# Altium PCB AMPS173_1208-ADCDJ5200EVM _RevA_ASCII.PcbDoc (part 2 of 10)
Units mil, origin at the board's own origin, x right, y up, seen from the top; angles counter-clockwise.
Board outline 10500 x 2750 mil, 14 copper layers (Top Copper, Layer 2 (GND1), Layer 3 (SIG1), Layer 4 (GND2, Layer 5 (PWR1), Layer 6 (GND3), Layer 7 (PWR/SIGNAL2), Layer 8 (PWR/SIGNAL3), Layer 9 (GND4), Layer 10 PWR2), Layer 11 (GND5), Layer 12 (SIG4), Layer 13 (GND6), Bottom Copper), stack 60.6 mil thick; 701 components, 826 nets, 3386 pads, 2128 vias.
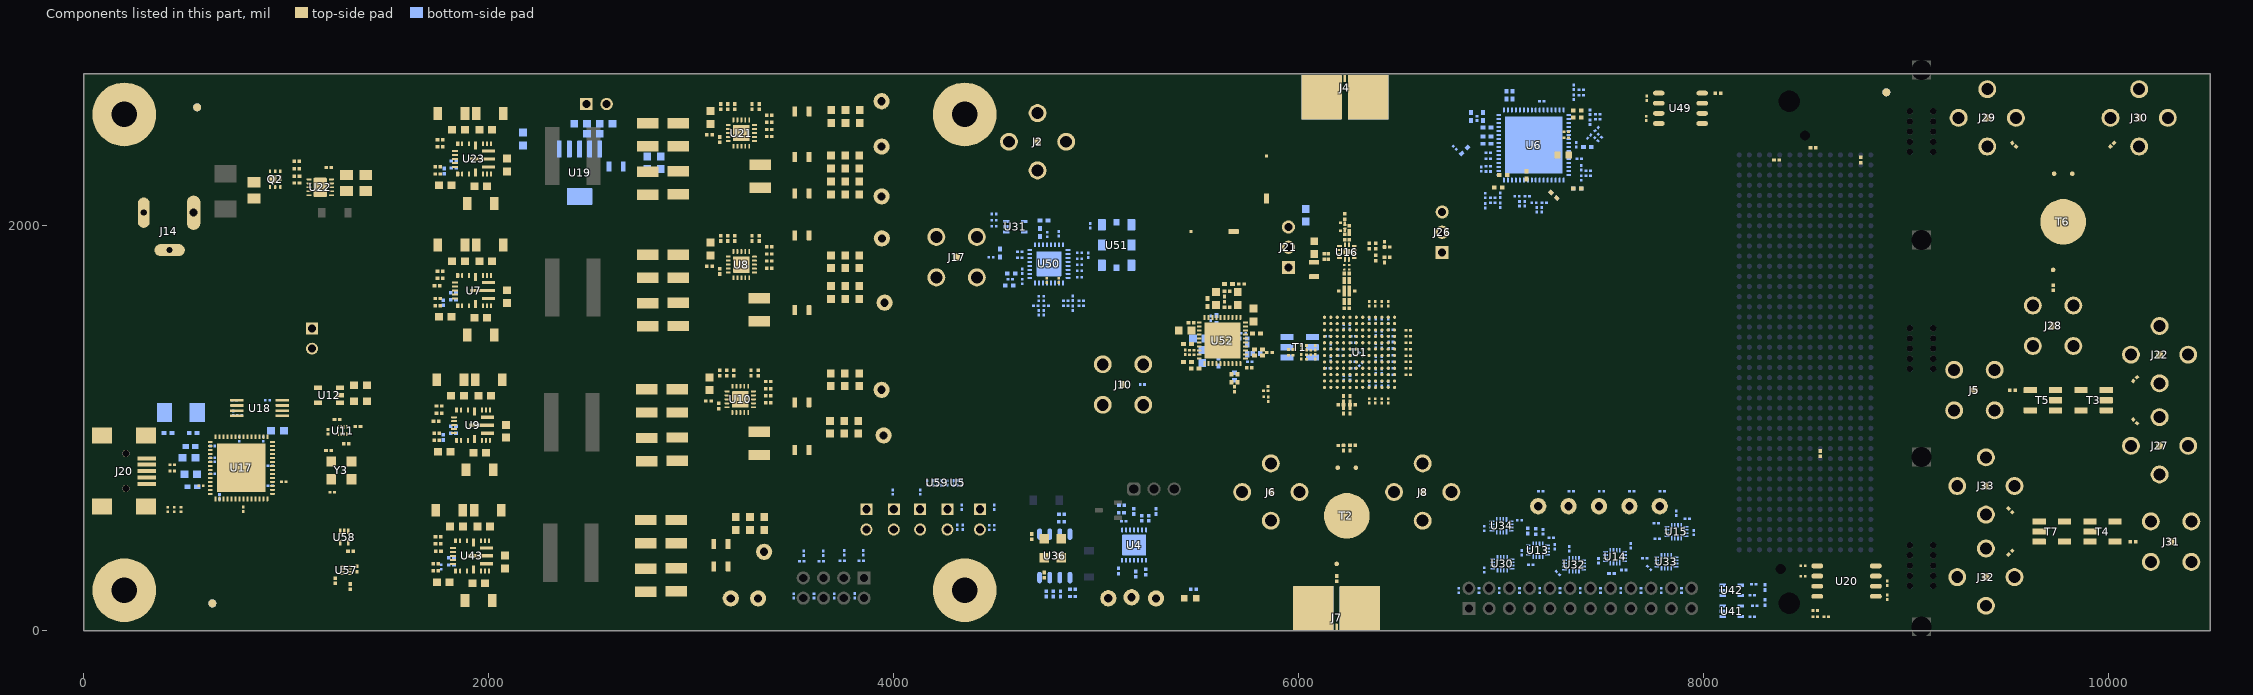
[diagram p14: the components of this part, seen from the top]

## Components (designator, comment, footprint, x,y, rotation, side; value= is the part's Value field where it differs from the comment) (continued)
R37 "CRCW02010000Z0ED" 0201L 7476.02,2550 r0 bottom value=0
R38 "CRCW02010000Z0ED" 0201L 7199.59,2078.93 r270 bottom value=0
R39 "CRCW02010000Z0ED" 0201L 6957.83,2113.09 r180 bottom value=0
R40 "CRCW02010000Z0ED" 0201L 7476.02,2525 r0 bottom value=0
R41 "CRCW02010000Z0ED" 0201L 7174.59,2078.93 r270 bottom value=0
R42 "CRCW02010000Z0ED" 0201L 7430,2271.02 r0 bottom value=0
R43 "RC0201FR-7D10KL" 0201L 7320,2465 r180 top value=10.0k
R44 "CRCW02010000Z0ED" 0201L 7430,2246.02 r0 bottom value=0
R45 "RC0201FR-7D240RL" 0201L 7438.19,2561.12 r270 bottom value=240
R46 "RC0201FR-7D240RL" 0201L 7438.19,2511.12 r90 bottom value=240
R47 "RC0201FR-7D240RL" 0201L 7211.4,2113.93 r180 bottom value=240
R48 "RC0201FR-7D240RL" 0201L 7161.4,2113.93 r0 bottom value=240
R49 "CRCW02010000Z0ED" 0201L 6957.83,2138.09 r180 bottom value=0
R50 "RC0201FR-7D240RL" 0201L 7395,2286.02 r270 bottom value=240
R51 "CRCW02010000Z0ED" 0201L 7487.31,2444.52 r315 bottom value=0
R52 "RC0201FR-7D240RL" 0201L 7395,2236.02 r90 bottom value=240
R53 "CRCW02010000Z0ED" 0201L 7469.63,2426.84 r315 bottom value=0
R54 "CRCW02010000Z0ED" 0201L 7890,198.98 r90 bottom value=0
R55 "RC0201FR-7D240RL" 0201L 7470.85,2477.55 r225 bottom value=240
R56 "RC0201FR-7D240RL" 0201L 7434.03,2440.74 r45 bottom value=240
R57 "RC0201FR-07120RL" 0201L 6995,2101.02 r90 bottom value=120
R58 "RC0201FR-07120RL" 0201L 6995,2151.02 r270 bottom value=120
R59 "CRCW02010000Z0ED" 0201L 7790,198.98 r90 bottom value=0
R60 "RC0201FS-7D100RL" 0201L 4340,511.02 r90 bottom value=100
R61 "RC0201FS-7D100RL" 0201L 7718,2629 r270 top value=100
R62 "CRCW02010000Z0ED" 0201L 7115,2108.98 r270 bottom value=0
R63 "CRCW02010000Z0ED" 0201L 7090,2108.98 r270 bottom value=0
R64 "RC0201FR-7D240RL" 0201L 7127.5,2145 r180 bottom value=240
R65 "RC0201FR-7D240RL" 0201L 7077.5,2145 r0 bottom value=240
R66 "RC0201FS-7D100RL" 0201L 7715,2530 r90 top value=100
R67 "RC0201FS-7D1KL" 0201 4682,465 r270 top value=1.00k
R68 "RC0201FS-7D1KL" 0201 4742.99,274.57 r90 top value=1.00k
R69 "RC0201FR-0747KL" 0201L 4313,511.02 r270 bottom value=47.0k
R70 "CRCW02010000Z0ED" 0201 5755.21,1298.79 r180 top value=27.0
R71 "RC0201FS-7D100RL" 0201L 7645,690 r180 bottom value=100
R72 "CRCW02010000Z0ED" 0201L 7690,198.98 r90 bottom value=0
R73 "CRCW02010000Z0ED" 0201 7130.98,493.39 r270 bottom value=10.0k
R74 "CRCW02010000Z0ED" 0201 7170.98,490.39 r270 bottom value=10.0k
R75 "RC0201FR-7D10KL" 0201L 7205.98,488.39 r270 bottom value=10.0k
R76 "CRCW02010000Z0ED" 0201L 7590,198.98 r90 bottom value=0
R77 "RC0201FR-7D10KL" 0201L 7605,300 r180 bottom value=10.0k
R78 "CRCW02010000Z0ED" 0201 7545,283 r0 bottom value=10.0k
R79 "CRCW02010000Z0ED" 0201L 7490,198.98 r90 bottom value=0
R80 "RC0201FR-7D10KL" 0201L 7765,530 r0 bottom value=10.0k
R81 "RC0201FR-7D10KL" 0201L 7865,580 r270 bottom value=10.0k
R82 "RC0201FS-7D100RL" 0201L 7795,690 r180 bottom value=100
R83 "RC0201FS-7D100RL" 0201L 3848.98,385 r90 bottom value=100
R84 "RC0201FR-0747KL" 0201L 3838.98,345 r0 bottom value=47.0k
R85 "CRCW02010000Z0ED" 0201L 7390,198.98 r90 bottom value=0
R86 "RC0201FR-7D49R9L" 0201L 7335,405 r90 bottom value=27.0
R87 "RC0201FS-7D100RL" 0201L 3755,386.02 r90 bottom value=100
R88 "CRCW02010000Z0ED" 0201L 7290,198.98 r90 bottom value=0
R89 "RC0201FR-0747KL" 0201L 3745,346.02 r0 bottom value=47.0k
R90 "RC0201FS-7D1KL" 0201L 4335,610 r270 bottom value=1.00k
R91 "RC0201FS-7D100RL" 0201L 3651.38,383.19 r90 bottom value=100
R92 "RC0201FS-7D4K99L" 0201 3385,1860.75 r180 top value=4.99k
R93 "RC0201FR-073RL" 0201 1747.99,1640.75 r180 top value=3.00
R94 "RC0201FS-7D4K99L" 0201 3140,1775 r90 top value=100k
R95 "RC0201FS-7D4K99L" 0201 1760,1740 r180 top value=4.99k
R96 "RC0201FR-7D49K9L" 0201 1825,1670 r0 bottom value=49.9k
R97 "RC0201FR-7D124KL" 0201 1775,1620 r90 bottom value=124k
R98 "CRCW02010000Z0ED" 0201 3385,1790.75 r0 top value=0
R99 "RC0201FS-7D4K99L" 0201 1760,1775 r180 top value=4.99k
R100 "CRCW02010000Z0ED" 0201 3145,1937.99 r270 top value=0
R101 "CRCW02010000Z0ED" 0201 3180,1937.99 r270 top value=0
R102 "CRCW02010000Z0ED" 0201 3215,1937.99 r270 top value=0
R103 "CRCW02010000Z0ED" 0201 8540,2385 r180 top value=0
R104 "RC0201FS-7D100RL" 0201 8360,2325 r180 top value=100
R105 "CRCW02010000Z0ED" 0201 8575,875 r90 top value=0
R106 "CRCW02010000Z0ED" 0201L 7190,198.98 r90 bottom value=0
R107 "RC0201FS-7D100RL" 0201 8775,2325 r270 top value=100
R108 "RC0201FR-0747KL" 0201L 3641.38,343.19 r0 bottom value=47.0k
R109 "RC0201FS-7D100RL" 0201L 3555,382.98 r90 bottom value=100
R110 "CRCW02010000Z0ED" 0201 3300,1937.99 r270 top value=0
R111 "CRCW02010000Z0ED" 0201 3335,1937.99 r270 top value=0
R112 "CRCW02010000Z0ED" 0201 3385,1895.75 r180 top value=0
R113 "RC0201FS-7D4K99L" 0201 3380,1195.75 r180 top value=4.99k
R114 "RC0201FR-073RL" 0201 1742.99,975.75 r180 top value=3.00
R115 "RC0201FR-7D49K9L" 0201 1825,975 r0 bottom value=49.9k
R116 "RC0201FS-7D4K99L" 0201 3135,1110 r90 top value=100k
R117 "RC0201FS-7D4K99L" 0201 1755,1075 r180 top value=4.99k
R118 "CRCW02010000Z0ED" 0201 3380,1125.75 r0 top value=0
R119 "RC0201FS-7D4K99L" 0201 1755,1110 r180 top value=4.99k
R120 "CRCW02010000Z0ED" 0201 3140,1272.99 r270 top value=0
R121 "RC0201FR-0741K2L" 0201 1775,955 r90 bottom value=41.2k
R122 "CRCW02010000Z0ED" 0201 3175,1272.99 r270 top value=0
R123 "CRCW02010000Z0ED" 0201 3210,1272.99 r270 top value=0
R124 "CRCW02010000Z0ED" 0201 3295,1272.99 r270 top value=0
R125 "CRCW02010000Z0ED" 0201 3330,1272.99 r270 top value=0
R126 "CRCW02010000Z0ED" 0201 3380,1230.75 r180 top value=0
R127 "RC0201FR-0733RL" 0201 1353.13,1008.87 r0 top value=33.0
R128 "RC0201FR-0733RL" 0201 1296,923 r0 top value=33.0
R129 "RC0201FR-0733RL" 0201 1241,247 r270 top value=33.0
R130 "RC0201FS-7D4K99L" 0201 3385,2510.75 r180 top value=4.99k
R131 "RC0201FR-073RL" 0201 1747.99,2290.75 r180 top value=3.00
R132 "RC0201FS-7D4K99L" 0201 3140,2425 r270 top value=100k
R133 "RC0201FR-7D49K9L" 0201 1827.01,2320 r0 bottom value=49.9k
R134 "RC0201FS-7D4K99L" 0201 1760,2390 r180 top value=4.99k
R135 "CRCW02010000Z0ED" 0201 3385,2440.75 r0 top value=0
R136 "RC0201FS-7D4K99L" 0201 1760,2425 r180 top value=4.99k
R137 "CRCW02010000Z0ED" 0201 3145,2587.99 r270 top value=0
R138 "RC0201FR-0719K1L" 0201 1780,2270 r90 bottom value=19.1k
R139 "CRCW02010000Z0ED" 0201 3180,2587.99 r270 top value=0
R140 "CRCW02010000Z0ED" 0201 3215,2587.99 r270 top value=0
R141 "CRCW02010000Z0ED" 0201 3300,2587.99 r270 top value=0
R142 "CRCW02010000Z0ED" 0201 3335,2587.99 r270 top value=0
R143 "CRCW02010000Z0ED" 0201 3385,2545.75 r180 top value=0
R144 "RC0201FR-7D1ML" 0201 1052.06,2211 r180 top value=1.00Meg
R145 "RC0201FR-7D45K3L" 0201 1209.56,2288 r0 top value=45.3k
R146 "RC0201FS-7D4K99L" 0201 1052.01,2245 r180 top value=4.99k
R147 "RC0201FR-0747KL" 0201L 3545,342.98 r0 bottom value=47.0k
R148 "CRCW02010000Z0ED" 0201L 7090,198.98 r90 bottom value=0
R149 "CRCW02010000Z0ED" 0201L 6990,198.98 r90 bottom value=0
R150 "CRCW02010000Z0ED" 0201L 6890,198.98 r90 bottom value=0
R151 "CRCW02010000Z0ED" 0201L 6790,198.98 r90 bottom value=0
R152 "RC0201FS-7D1KL" 0201L 3807,173.02 r90 bottom value=1.00k
R153 "RC0201FR-7D100RL" 0201L 579,716 r180 top value=100
R155 "RC0201FR-7D100RL" 0201L 788.5,600.5 r270 top value=100
R156 "RC0201FR-7D10RL" 0201L 436.02,820 r0 top value=10.0
R157 "RC0201FR-7D10RL" 0201L 436,789 r0 top value=10.0
R158 "RC0201FS-7D1KL" 0201L 3706,172.02 r90 bottom value=1.00k
R159 "RC0201FS-7D1KL" 0201L 3606,172.02 r90 bottom value=1.00k
R160 "RC0201FR-7D12KL" 0201L 636,834 r180 bottom value=12.0k
R161 "RC0201FS-7D1KL" 0201L 3506,172.02 r90 bottom value=1.00k
R162 "RC0201FR-7D12KL" 0201L 414,599 r90 top value=12.0k
R163 "RC0201FR-7D100RL" 0201L 987,735.5 r0 top value=100
R164 "RC0201JR-071ML" 0201 4827.99,538.82 r180 bottom value=1.0Meg
R165 "CRCW02010000Z0ED" 0201L 447,598.98 r90 top value=0
R166 "RC0201FR-7D10KL" 0201L 480,599 r270 top value=10.0k
R167 "RC0201FR-7D10KL" 0201L 744,1138.18 r0 bottom value=10.0k
R168 "RC0201FR-7D10KL" 0201L 745,1113 r0 bottom value=10.0k
R169 "RC0201FR-7D10KL" 0201L 769,1064 r0 bottom value=10.0k
R170 "RC0201FR-7D2K2L" 0201L 737,1075 r90 bottom value=2.20k
R171 "CRCW02010000Z0ED" 0201L 6070.02,1364 r0 top value=0
R172 "CRCW02010000Z0ED" 0201L 6013,1374.98 r270 top value=0
R174 "CRCW02010000Z0ED" 0201L 6070.02,1386 r0 top value=0
R175 "RC0201FR-7D10KL" 0201L 1206,983 r270 top value=10.0k
R176 "RC0201JR-071ML" 0201 4882.99,204.25 r180 bottom value=1.0Meg
R177 "RC0201FS-7D8K06L" 0201 4752.99,182.56 r270 bottom value=8.06k
R178 "RC0201FS-7D100RL" 0201L 7247,460 r0 bottom value=100
R179 "RC0603FR-074K7L" 0603 6035,2052.47 r90 bottom value=4.70k
R180 "ERJ-1GNJ5R1C" FP-ERJ-1GNJ5R1C_0201-MFG 6248.92,1795 r270 top
R181 "RC0201FR-078R66L" 0201 6248.92,1707.99 r270 top value=8.66
R182 "RC0201FR-078R66L" 0201 6248.92,1647.99 r270 top value=8.66
R183 "RC0201JR-0710RL" 0201 6248.92,1605 r270 top value=10
R184 "RC0201FR-07140RL" 0201 6262.72,1677.98 r180 top value=140
R185 "ERJ-1GNJ5R1C" FP-ERJ-1GNJ5R1C_0201-MFG 6224.92,1795 r270 top
R186 "RC0201FR-078R66L" 0201 6224.92,1707.99 r270 top value=8.66
R187 "RC0201FR-078R66L" 0201 6224.92,1647.99 r270 top value=8.66
R188 "RC0201JR-0710RL" 0201 6224.92,1605 r270 top value=10
R189 "RC0201FR-07140RL" 0201 6211.14,1677.98 r0 top value=140
R193 "ERJ-1GEF49R9C" 0201 6248.84,1986.93 r270 top value=49.9
R194 "ERJ-1GE0R00C" 0201 6436.49,1894.93 r180 top value=0
R195 "ERJ-1GE0R00C" 0201 6423.49,1907.93 r90 top value=0
R196 "ERJ-1GE0R00C" 0201 6436.49,1844.93 r180 top value=0
R197 "ERJ-1GE0R00C" 0201 6423.49,1831.94 r270 top value=0
R198 "RC0603FR-0732K4L" 0603 2516.5,2454 r180 bottom value=32.4k
R199 "RC0603JR-0710KL" 0603 2579.5,2504 r180 bottom value=10k
R207 "RC0201FS-7D100RL" 0201L 7919,554 r0 bottom value=100
R215 "CRCW02010000Z0ED" 0201L 8605,70 r180 top value=0
R216 "RC0201FR-071K33L" 0201 4822.99,182.56 r90 bottom value=1.33k
R217 "CRCW02010000Z0ED" 0201L 8550,70 r0 top value=0
R218 "CRCW02010000Z0ED" 0201L 8905,165 r270 top value=0
R219 "RC0201FS-7D100RL" 0201L 7195,690 r180 bottom value=100
R220 "CRCW02010000Z0ED" 0201L 8905,235 r90 top value=0
R226 "CRCW02010000Z0ED" 0201L 7394.19,2671.98 r0 bottom value=0
R227 "CRCW02010000Z0ED" 0201L 7394.19,2644.98 r0 bottom value=0
R228 "RC0201FR-073RL" 0201 1737.99,330.75 r180 top value=3.00
R229 "RC0201FR-7D49K9L" 0201 1815,360 r0 bottom value=49.9k
R230 "RC0201FS-7D4K99L" 0201 1750,430 r180 top value=4.99k
R231 "RC0201FS-7D4K99L" 0201 1750,465 r180 top value=4.99k
R232 "RC0201FR-07499KL" 0201L 1765,315 r90 bottom value=499k
R233 "RC0201FR-0733RL" 0201 1316,218 r270 top value=33.0
R238 "RC0201FR-7D240RL" 0201L 7358.19,2683.98 r270 bottom value=240
R239 "RC0201FS-7D100RL" 0201L 4635,1725 r270 bottom value=100
R240 "CRCW02010000Z0ED" 0201L 4848.98,1630 r0 bottom value=0
R241 "RC0201FS-7D100RL" 0201L 4917.09,1745.28 r0 bottom value=100
R242 "CRCW02010000Z0ED" 0201L 4848.98,1605 r0 bottom value=0
R243 "RC0201FR-07160RL" 0201L 4883.98,1592.5 r90 bottom value=160
R244 "RC0201FR-07160RL" 0201L 4883.98,1642.5 r270 bottom value=160
R245 "CRCW02010000Z0ED" 0201L 4480,1845 r0 bottom value=0
R246 "CRCW02010000Z0ED" 0201L 4740,1641.02 r270 bottom value=0
R247 "CRCW02010000Z0ED" 0201L 4715,1641.02 r270 bottom value=0
R248 "ERJ-2RKF49R9X" 0402L 4525,1865 r270 bottom value=49.9
R249 "RC0201FR-07160RL" 0201L 4701.48,1606.02 r0 bottom value=160
R250 "RC0201FR-07160RL" 0201L 4752.5,1606.02 r180 bottom value=160
R251 "RC0201FS-7D100RL" 0201L 4960,1855 r270 bottom value=100
R252 "CRCW040249R9FKED" 0402L 5801.02,1388.79 r0 top value=49.9
R253 "CRCW040249R9FKED" 0402L 5801.02,1359.79 r0 top value=49.9
R254 "RC0201FR-7D49R9L" 0201L 4130,685 r270 bottom value=49.9
R255 "RC0201FR-7D10KL" 0201L 3995,685 r90 bottom value=10.0k
R256 "RC0201FR-7D240RL" 0201L 7358.19,2633.98 r90 bottom value=240
R258 "CRCW040249R9FKED" 0402L 5667.41,1247.19 r270 top value=49.9
R259 "CRCW040249R9FKED" 0402L 5696.71,1247.19 r270 top value=49.9
R262 "RC0201FR-7D10KL" 0201 5468.21,1521.79 r180 top value=10.0k
R263 "RC0201FR-7D270RL" 0201 5633.21,1637.79 r90 top value=22.1
R264 "RC0201FR-7D120RL" 0201 5717.2,1712.79 r180 top value=15.4
R265 "RC0201FS-7D100RL" 0201L 5439.21,1374.79 r90 top value=100
R277 "RC0201FR-7D47KL" 0201L 4495,1998.19 r180 bottom value=47.0k
R278 "RC0201FS-7D100RL" 0201L 4495,2028.19 r180 bottom value=100
R279 "RC0201FS-7D1KL" 0201L 4495,2058.19 r0 bottom value=1.00k
R280 "RC0201FS-7D4K99L" 0201 1740,1035 r180 top value=4.99k
R305 "CRCW02010000Z0ED" 0201L 7145,325 r0 bottom value=27.0
R359 "RC0201FR-07120RL" 0201L 6920,2099.55 r90 bottom value=120
R360 "RC0201FR-07120RL" 0201L 6920,2149.55 r270 bottom value=120
R451 "RC0201FS-7D100RL" 0201L 6900,2280 r270 bottom value=100
R750 "RC0201FR-7D10KL" 0201L 7709,358 r0 bottom value=10.0k
R801 "RC0201FR-7D10KL" 0201L 1226.89,684.44 r180 top value=10.0k
R804 "CRCW02010000Z0ED" 0201L 8246.98,229.41 r0 bottom value=0
R805 "RC0201FR-7D10KL" 0201 8301.98,214.41 r270 bottom value=10.0k
R807 "CRCW02010000Z0ED" 0201L 8490,270 r0 top value=0
R808 "CRCW02010000Z0ED" 0201L 8490,320 r0 top value=0
R851 "RC0201FR-7D10KL" 0201 8301.98,139.41 r90 bottom value=10.0k
R852 "CRCW02010000Z0ED" 0201L 8251.98,124.41 r0 bottom value=0
R888 "RC0201FS-7D4K99L" 0201 1750.79,392.43 r180 top value=4.99k
R950 "RC0201FS-7D4K99L" 0201 1745.18,1703.43 r180 top value=4.99k
T1 "TCM1-83X+" MNC_TCM1-83X+ 6004.4,1400 r270 bottom
T2 "BAL-0020SLG" FP-BAL-0020SLG_SMT_BALUN_12MM70_5MM08-MFG 6237,567.54 r180 top
T3 "TC1-1-13M+" FP-TC1-1-13M+_SMT_3MM81_3MM81-MFG 9925,1138.48 r270 top
T4 "TC1-1-13M+" FP-TC1-1-13M+_SMT_3MM81_3MM81-MFG 9969,490 r90 top
T5 "TC1-1-13M+" FP-TC1-1-13M+_SMT_3MM81_3MM81-MFG 9675,1138.48 r270 top
T6 "BAL-0020SLG" FP-BAL-0020SLG_SMT_BALUN_12MM70_5MM08-MFG 9775,2019.48 r180 top
T7 "TC1-1-13M+" FP-TC1-1-13M+_SMT_3MM81_3MM81-MFG 9719,490 r90 top
TP1 "5000" Keystone5000 3195,160 r180 top
TP2 "5000" Keystone5000 5059.25,160.47 r180 top
TP3 "5000" Keystone5000 5174.25,165.47 r180 top
TP4 "5000" Keystone5000 5295,160 r180 top
TP5 "5000" Keystone5000 3955,1620 r270 top
TP6 "5001" Keystone5001 3330,160 r270 top
TP7 "5000" Keystone5000 3360,390 r270 top
TP8 "5002" Keystone5002 7332.5,615 r180 top
TP9 "5000" Keystone5000 3940,1190 r270 top
TP10 "5000" Keystone5000 3940,2615 r270 top
TP11 "5000" Keystone5000 3940,2390.96 r270 top
TP12 "5002" Keystone5002 7482.5,615 r180 top
TP13 "5002" Keystone5002 7632.5,615 r180 top
TP14 "5002" Keystone5002 7782.5,615 r180 top
TP15 "5002" Keystone5002 7182.5,615 r180 top
TP16 "5000" Keystone5000 3941,1938.02 r90 top
TP20 "5000" Keystone5000 3950,965 r270 top
TP21 "5000" Keystone5000 3940,2145 r270 top
U1 "ADC12DJ3200AAVR" AAV0144A 6300,1375 r0 top locked
U4 "LM95233CISD/NOPB" NHL0014B 5187.25,423.47 r270 bottom
U5 "SN74AUP1G126DRYR" DRY0006A 4315,730 r270 bottom
U6 "LMK04828BISQE/NOPB" NKD0064A 7160.31,2398.82 r180 bottom locked
U7 "LMS3635MQRNLRQ1" RNL0022A 1925,1680 r90 top
U8 "TPS7A8400RGRR" RGR0020A 3247,1808 r180 top
U9 "LMS3635MQRNLRQ1" RNL0022A 1920,1015 r90 top
U10 "TPS7A8400RGRR" RGR0020A 3242,1143 r180 top
U11 "SN74LVC1G74DQER" DQE0008A 1278.13,988.87 r90 top
U12 "TLV70133DBVT" DBV0005A_N 1211,1163 r180 top
U13 "SN74AVC4T774RSVR" RSV0016A 7180.75,398.35 r270 bottom
U14 "SN74AVC4T774RSVR" RSV0016A 7562.13,366.5 r90 bottom
U15 "SN74AVC4T774RSVR" RSV0016A 7865,490 r270 bottom
U16 "LMH81XX_COB" LMH81XX_COB 6237.08,1870.09 r180 top
U17 "FT4232H-56Q-TRAY" VQFN-56 778.36,804.5 r0 top locked
U18 "93LC46B-I/ST" TSSOP-8 868.2,1099.8 r0 top
U19 "TPS7A4501DCQT" DCQ0006A_N 2448,2261.87 r270 bottom
U20 "24LC65-I/SM" SOIC127P800X216-8N 8705,245 r180 top locked
U21 "TPS7A8400RGRR" RGR0020A 3247,2458 r180 top
U22 "TPS259261DRCR" DRC0010J 1167.56,2190 r0 top
U23 "LMS3635MQRNLRQ1" RNL0022A 1925,2330 r90 top
U30 "SN74CBTLV3257RSVR" RSV0016A 7005,330 r270 bottom
U31 "SN74LV1T125DCKR" DCK0005A_N 4600,1995 r0 bottom
U32 "SN74CBTLV3257RSVR" RSV0016A 7360,325 r270 bottom
U33 "SN74CBTLV3257RSVR" RSV0016A 7815,340 r270 bottom
U34 "SN74AVC4T774RSVR" RSV0016A 7002,518 r90 bottom
U36 "LMC6762AIM/NOPB" D0008A_N 4795,370 r270 bottom
U41 "SN74LVC1G125DCKR" DCK0005A_N 8138,96.73 r0 bottom
U42 "SN74LVC1G125DCKR" DCK0005A_N 8138,199.41 r0 bottom
U43 "LMS3655MQRNLRQ1" RNL0022A 1915,370 r90 top
U49 "DS90LV028AQMA/NOPB" D0008A_N 7885,2580 r0 top locked
U50 "LMK00304SQ/NOPB" RTV0032A 4766.3,1811.57 r90 bottom
U51 "LMK61E2-SIAR" SIA0008B 5100,1905 r180 bottom
U52 "LMX2594RHAR" RHA0040H 5623.03,1433.38 r0 top
U57 "SN74LVC1G74DQER" DQE0008A 1296,298 r0 top
U58 "SN74LVC1G04DRLR" DRL0005A 1286,463 r270 top
U59 "SN74AUP1G08DRYR" DRY0006A 4215,730 r270 bottom
Y1 "ABM3-12.000MHZ-D2Y-T" XTAL_ABM3 479.29,1078 r180 bottom
Y3 "FXO-HC536R-1" FOX_FXO-HC5 1272.13,791.87 r90 top
ZZ1 "This Assembly Note is for PCB labels only" AssemblyNoteLabel 560,6670 r0 top
ZZ2 "These assemblies are ESD sensitive, ESD precautions shall be observed." AssemblyNote 560,6590 r0 top
ZZ3 "These assemblies must be clean and free from flux and all contaminants. Use of no clean flux is not acceptable." AssemblyNote 560,6430 r0 top
ZZ4 "These assemblies must comply with workmanship standards IPC-A-610 Class 2, unless otherwise specified." AssemblyNote 560,6510 r0 top

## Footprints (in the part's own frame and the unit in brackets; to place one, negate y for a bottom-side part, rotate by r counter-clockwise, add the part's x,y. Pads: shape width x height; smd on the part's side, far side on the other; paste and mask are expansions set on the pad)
0201 [mm] "Data from Kemet datasheet CC101_COM dated 7/28/11"
  rect 0.46x0.42 smd mask+0.048: 1(-0.33,0) 2(0.33,0)
  body extent -0.31,-0.16 0.31,0.16, height 0.26
0201_033 [mm] "SMD, 2-Leads, Height 0.33mm"
  rect 0.46x0.42 smd mask+0.048: 1(-0.33,0) 2(0.33,0)
  body extent -0.31,-0.16 0.31,0.16, height 0.33
0201_033L [mm] "0201"
  rect 0.36x0.32 smd mask+0.048: 1(-0.28,0) 2(0.28,0)
  body extent -0.31,-0.16 0.31,0.16, height 0.33
0201L [mm] "Data from Kemet datasheet CC101_COM dated 7/28/11"
  rect 0.36x0.32 smd mask+0.048: 1(-0.28,0) 2(0.28,0)
  body extent -0.31,-0.16 0.31,0.16, height 0.26
0402 [mm] "0402 from SM-752 data"
  rect 0.8x0.6 smd: 1(-0.6,0) 2(0.6,0)
  silkscreen extent -1.22,-0.52 1.22,0.52, body extent -0.55,-0.3 0.55,0.3, height 0.6
0402L [mm] "0402 from SM-752 data"
  rect 0.6x0.5 smd: 1(-0.5,0) 2(0.5,0)
  body extent -0.55,-0.3 0.55,0.3, height 0.6
0603 [mm] "0603 from SM-752 data"
  rect 1x0.95 smd: 1(-0.8,0) 2(0.8,0)
  silkscreen extent -1.52,-0.69 1.52,0.69, body extent -0.87,-0.47 0.87,0.47, height 1
0603L [mm] "0603 from SM-752 data"
  rect 0.8x0.85 smd: 1(-0.7,0) 2(0.7,0)
  silkscreen extent -0.07,-0.32 0.07,0.32, body extent -0.87,-0.47 0.87,0.47, height 1
0805_HV [mil] "0805 with 30mil clearance between pads"
  rect 50x63 smd: 1(-40,0) 2(40,0)
  silkscreen extent -74,-40 74,40, body extent -43,-29 43,29, height 57
1206_180 [mm] "1206_180"
  rect 1.1x1.6 smd: 1(-1.7,0) 2(1.7,0)
  silkscreen extent -0.9,-1 0.9,1, body extent -1.75,-0.95 1.75,0.95, height 1.8
1210_270 [mm] "1210"
  rect 1.3x2.7 smd: 1(-1.45,0) 2(1.45,0)
  silkscreen extent -2.32,-1.57 2.32,1.57, body extent -1.7,-1.35 1.7,1.35, height 2.7
AAV0144A [mm] "BGA, 144-Leads, Body 10x10mm, Pitch 0.8mm"
  round 0.4 smd: A1(-4.4,4.4) A2(-3.6,4.4) A3(-2.8,4.4) A4(-2,4.4) A5(-1.2,4.4) A6(-0.4,4.4) A7(0.4,4.4) A8(1.2,4.4) A9(2,4.4) A10(2.8,4.4) A11(3.6,4.4) A12(4.4,4.4) B1(-4.4,3.6) B2(-3.6,3.6) B3(-2.8,3.6) B4(-2,3.6) B5(-1.2,3.6) B6(-0.4,3.6) B7(0.4,3.6) B8(1.2,3.6) B9(2,3.6) B10(2.8,3.6) B11(3.6,3.6) B12(4.4,3.6) C1(-4.4,2.8) C2(-3.6,2.8) C3(-2.8,2.8) C4(-2,2.8) C5(-1.2,2.8) C6(-0.4,2.8) C7(0.4,2.8) C8(1.2,2.8) C9(2,2.8) C10(2.8,2.8) C11(3.6,2.8) C12(4.4,2.8) D1(-4.4,2) D2(-3.6,2) D3(-2.8,2) D4(-2,2) D5(-1.2,2) D6(-0.4,2) D7(0.4,2) D8(1.2,2) D9(2,2) D10(2.8,2) D11(3.6,2) D12(4.4,2) E1(-4.4,1.2) E2(-3.6,1.2) E3(-2.8,1.2) E4(-2,1.2) E5(-1.2,1.2) E6(-0.4,1.2) E7(0.4,1.2) E8(1.2,1.2) E9(2,1.2) E10(2.8,1.2) E11(3.6,1.2) E12(4.4,1.2) F1(-4.4,0.4) F2(-3.6,0.4) F3(-2.8,0.4) F4(-2,0.4) F5(-1.2,0.4) F6(-0.4,0.4) F7(0.4,0.4) F8(1.2,0.4) F9(2,0.4) F10(2.8,0.4) F11(3.6,0.4) F12(4.4,0.4) G1(-4.4,-0.4) G2(-3.6,-0.4) G3(-2.8,-0.4) G4(-2,-0.4) G5(-1.2,-0.4) G6(-0.4,-0.4) G7(0.4,-0.4) G8(1.2,-0.4) G9(2,-0.4) G10(2.8,-0.4) G11(3.6,-0.4) G12(4.4,-0.4) H1(-4.4,-1.2) H2(-3.6,-1.2) H3(-2.8,-1.2) H4(-2,-1.2) H5(-1.2,-1.2) H6(-0.4,-1.2) H7(0.4,-1.2) H8(1.2,-1.2) H9(2,-1.2) H10(2.8,-1.2) H11(3.6,-1.2) H12(4.4,-1.2) J1(-4.4,-2) J2(-3.6,-2) J3(-2.8,-2) J4(-2,-2) J5(-1.2,-2) J6(-0.4,-2) J7(0.4,-2) J8(1.2,-2) J9(2,-2) J10(2.8,-2) J11(3.6,-2) J12(4.4,-2) K1(-4.4,-2.8) K2(-3.6,-2.8) K3(-2.8,-2.8) K4(-2,-2.8) K5(-1.2,-2.8) K6(-0.4,-2.8) K7(0.4,-2.8) K8(1.2,-2.8) K9(2,-2.8) K10(2.8,-2.8) K11(3.6,-2.8) K12(4.4,-2.8) L1(-4.4,-3.6) L2(-3.6,-3.6) L3(-2.8,-3.6) L4(-2,-3.6) L5(-1.2,-3.6) L6(-0.4,-3.6) L7(0.4,-3.6) L8(1.2,-3.6) L9(2,-3.6) L10(2.8,-3.6) L11(3.6,-3.6) L12(4.4,-3.6) M1(-4.4,-4.4) M2(-3.6,-4.4) M3(-2.8,-4.4) M4(-2,-4.4) M5(-1.2,-4.4) M6(-0.4,-4.4) M7(0.4,-4.4) M8(1.2,-4.4) M9(2,-4.4) M10(2.8,-4.4) M11(3.6,-4.4) M12(4.4,-4.4)
  silkscreen extent -5.4,-5.07 5.07,5.17, body extent -5,-5 5,5, height 1.77
AssemblyNote [mil] "Assembly Note"
AssemblyNoteLabel [mil] "Assembly Note for PCB Labels"
CAPC0603X33X15LL03T05 [mm] "Chip Capacitor, 2-Leads, Body 0.60x0.30mm, IPC High Density"
  rect 0.36x0.32 smd: 1(-0.28,0) 2(0.28,0)
  body extent -0.32,-0.17 0.32,0.17, height 0.33
CE_Mark_5mm [mil] "Minimum text height for CE Mark"
  silkscreen extent -138,-98 138,98
CONN_5-146261-1 [mm] "Sullins"
  rect 1.5x1.5 hole 1.02: 1(-1.27,0)
  round 1.5 hole 1.02: 2(1.27,0)
  silkscreen extent -3.68,-1.27 2.54,1.27, body extent -2.51,-1.27 2.51,1.27, height 10.87
CONN_LTI_SASF546-P26-X1 [mm]
  round 0.914 smd: 1(0,0)
  round 2.25 hole 1.5 mask+0.051: 2(-2.54,2.54) 3(-2.54,-2.54) 4(2.54,-2.54) 5(2.54,2.54)
  silkscreen extent -3.4,-3.4 3.4,3.4, body extent -3.18,-3.18 3.18,3.18, height 12.53
CONN_RAPC722X [mm] "Conn_DC Jack"
  oval 1.7x4.3 hole 1.01 slot 3.56 at 90 deg: 1(-13.741,0)
  oval 1.5x3.8 hole 0.76 slot 3.05 at 90 deg: 2(-7.493,0)
  oval 3.8x1.5 hole 0.76 slot 3.05 at 0 deg: 3(-10.744,4.7)
  silkscreen extent -14.48,-4.57 0.25,4.57, body extent -14.5,-4.57 0.23,4.83, height 11.18
CONN_USB-Mini-B-1734035-2 [mm] "Tyco Connectivity recommended land pattern"
  rect 0.5x2.3 smd: 1(-1.6,2.6) 2(-0.8,2.6) 3(0,2.6) 4(0.8,2.6) 5(1.6,2.6)
  rect 2x2.5 smd: 6(4.45,2.5) 7(4.45,-3) 8(-4.45,-3) 9(-4.45,2.5)
  round 0.9 hole 0.9 unplated: 10(2.2,0) 11(-2.2,0)
  silkscreen extent -5,-5 4.9,4.19, body extent -4.95,-5.9 4.95,3.3, height 4.1
D0008A_N [mm] "SOIC, 8-Leads, Body 4.9x3.9mm, Pitch 1.27mm, IPC Medium Density"
  oval 1.45x0.6 smd: 1(-2.725,1.905) 2(-2.725,0.635) 3(-2.725,-0.635) 4(-2.725,-1.905) 5(2.725,-1.905) 6(2.725,-0.635) 7(2.725,0.635) 8(2.725,1.905)
  silkscreen extent -3.3,-2.5 0.9,2.5, body extent -3,-2.45 3,2.45, height 1.63
DBV0005A_N [mm] "SOT23, 5-Leads, Body 2.9x1.6mm, Pitch 0.95mm, Lead Span 2.8mm, IPC Medium Density"
  rrect17% 1x0.6 smd: 1(-1.375,0.95) 2(-1.375,0) 3(-1.375,-0.95) 4(1.375,-0.95) 5(1.375,0.95)
  silkscreen extent -0.25,-1.55 0.25,1.55, body extent -1.42,-1.46 1.42,1.46, height 1.09
DCK0005A_N [mm] "SOT353, 5-Leads, Body 2x1.3mm, Pitch 0.65mm, Lead Span 2.1mm, IPC Medium Density"
  rrect25% 0.85x0.4 smd: 1(-1.125,0.65) 2(-1.125,0) 3(-1.125,-0.65) 4(1.125,-0.65) 5(1.125,0.65)
  silkscreen extent -1.48,-1.02 0.55,1.1, body extent -1.14,-1 1.14,1, height 0.95
DCQ0006A_N [mm] "SOT223, 6-Leads, Body 6.6x7.3mm (max), Pitch 1.27mm, IPC Medium Density"
  rrect17% 2.1x0.6 smd: 1(-2.975,2.54) 2(-2.975,1.27) 3(-2.975,0) 4(-2.975,-1.27) 5(-2.975,-2.54)
  rrect5% 2.1x3.2 smd: 6(2.975,0)
  silkscreen extent -1.5,-3.27 1.5,3.27, body extent -3.54,-3.25 3.54,3.25, height 1.8
DQE0008A [mm] "SON, 8-Leads, Body 1.4x1mm, Pitch 0.35mm, TI Recommended"
  rect 0.6x0.16 smd: 1(-0.4,0.525)
  rect 0.5x0.16 smd: 2(-0.45,0.175) 3(-0.45,-0.175) 4(-0.45,-0.525) 5(0.45,-0.525) 6(0.45,-0.175) 7(0.45,0.175) 8(0.45,0.525)
  silkscreen extent -0.7,-0.85 0.4,0.85, body extent -0.53,-0.72 0.53,0.73, height 0.41
DQK0006C [mm] "WSON"
  rrect34% 0.7x0.29 on Top Paste: 0(0.095,-0.65)
  rrect0% 0.9x0.86 on Top Paste: 0_1(0,0.325)
  rrect33% 0.45x0.3 smd: 1(-0.975,0.65) 2(-0.975,0) 3(-0.975,-0.65) 4(0.975,-0.65) 5(0.975,0) 6(0.975,0.65)
  rrect33% 0.75x0.3 smd paste-0.15: 7(0.095,-0.65)
  rrect11% 1x0.95 smd paste-0.5: 8(0,0.325)
  silkscreen extent -1.15,-1.15 1.15,1.15, body extent -1,-1 1,1, height 0.82
DRC0010J [mm] "VSON-10"
  rrect42% 0.6x0.24 smd: 1(-1.4,1) 2(-1.4,0.5) 3(-1.4,0) 4(-1.4,-0.5) 5(-1.4,-1) 6(1.4,-1) 7(1.4,-0.5) 8(1.4,0) 9(1.4,0.5) 10(1.4,1)
  rrect12% 1.65x2.4 smd paste-1 mask-2: 11(0,0)
  Top Copper region: -0.375,-1.65 -0.375,-1.2 -0.775,-1.2 -0.794,-1.196 -0.81,-1.185 -0.821,-1.169 -0.825,-1.15 -0.825,-1.15 -0.825,1.15 -0.821,1.169 -0.81,1.185 -0.794,1.196 -0.775,1.2 -0.775,1.2 -0.375,1.2 -0.375,1.65 -0.371,1.669 -0.36,1.685 -0.344,1.696 -0.325,1.7 -0.325,1.7 -0.325,1.7 -0.175,1.7 -0.175,1.7 -0.156,1.696 -0.14,1.685 -0.129,1.669 -0.125,1.65 -0.125,1.65 -0.125,1.2 0.125,1.2 0.125,1.65 0.129,1.669 0.14,1.685 0.156,1.696 0.175,1.7 0.175,1.7 0.175,1.7 0.325,1.7 0.325,1.7 0.344,1.696 0.36,1.685 0.371,1.669 0.375,1.65 0.375,1.65 0.375,1.2 0.775,1.2 0.794,1.196 0.81,1.185 0.821,1.169 0.825,1.15 0.825,1.15 0.825,-1.15 0.821,-1.169 0.81,-1.185 0.794,-1.196 0.775,-1.2 0.775,-1.2 0.375,-1.2 0.375,-1.65 0.371,-1.669 0.36,-1.685 0.344,-1.696 0.325,-1.7 0.325,-1.7 0.175,-1.7 0.156,-1.696 0.14,-1.685 0.129,-1.669 0.125,-1.65 0.125,-1.65 0.125,-1.2 -0.125,-1.2 -0.125,-1.65 -0.129,-1.669 -0.14,-1.685 -0.156,-1.696 -0.175,-1.7 -0.175,-1.7 -0.325,-1.7 -0.344,-1.696 -0.36,-1.685 -0.371,-1.669 -0.375,-1.65
  body extent -1.5,-1.5 1.5,1.5, height 1
DRL0005A [mm] "SOTFL, 5-Flat Leads, Body 1.2x1.6x0.6mm, Pitch 0.5mm, TI recommended"
  rrect33% 0.67x0.3 smd: 1(-0.74,0.5) 2(-0.74,0) 3(-0.74,-0.5) 4(0.74,-0.5) 5(0.74,0.5)
  silkscreen extent -0.9,-0.95 0.5,0.95, body extent -0.85,-0.85 0.85,0.85, height 0.62
DRY0006A [mm] "USON-6"
  rrect67% 0.45x0.3 smd paste-0.05 mask-0.05: 1(-0.275,0.5)
  rrect67% 0.4x0.3 smd paste-0.05 mask-0.05: 2(-0.3,0) 3(-0.3,-0.5) 4(0.3,-0.5) 5(0.3,0) 6(0.3,0.5)
  body extent -0.5,-0.72 0.5,0.72, height 0.58
FCC_disclaimer [mil]
Fiducial10-20 [mm]
  round 1 smd mask+0.5: 1(0,0)
  Top Copper keep-out circle w1.178: c0,0 r0.5
FOX_FXO-HC5 [mm] "SMT, 4-Leads, Body 5.15x3.35mm"
  rect 1.29x1.24 smd: 1(-1.125,1.27) 2(-1.125,-1.27) 3(1.125,-1.27) 4(1.125,1.27)
  silkscreen extent -2.07,-2.87 2.07,2.87, body extent -1.67,-2.58 1.68,2.57, height 1.4
FP-1092-01A-6_RF_JACK_18MM94_12MM7-MFG [mil]
  rrect33% 12x35 smd paste-39370.1 mask+0: 1(0,-190.5)
  rrect2% 200x220 smd paste-39370.1 mask+0: 2(-115,-283) 3(115,-283)
  rrect2% 200x220 smd far side paste-39370.1 mask+0: 2(-115,-283) 3(115,-283)
  silkscreen extent -250,-373 250,-333, body extent -254,-397 254,377, height 10
FP-BAL-0020SLG_SMT_BALUN_12MM70_5MM08-MFG [mil]
  round 22.48 smd paste+0 mask+0: 1(50,237.5) 2(-45,-237.5) 3(45,-237.5)
  round 225 smd paste-39370.1 mask+0: 4(0,0)
  Top Copper region: -125,-275 -125,275 35,275 35,270.3 32.96,259.41 27.1,250 27.1,250 25,250 25,240 27.48,229.15 34.41,220.45 44.44,215.63 55.56,215.63 65.59,220.45 72.52,229.15 75,240 75,240 75,250 72.9,250 67.04,259.41 65,270.3 65,270.3 65,275 125,275 125,-275 60,-275 60,-272.4 62.61,-260.13 70,-250 70,-250 70,-240 66.64,-227.51 57.49,-218.38 45,-215.03 32.51,-218.38 23.36,-227.51 20,-240 20,-240 20,-250 27.39,-260.13 30,-272.4 30,-272.4 30,-275 -30,-275 -30,-272.4 -27.39,-260.13 -20,-250 -20,-250 -20,-240 -22.48,-229.15 -29.41,-220.45 -39.44,-215.63 -50.56,-215.63 -60.59,-220.45 -67.52,-229.15 -70,-240 -70,-240 -70,-250 -62.61,-260.13 -60,-272.4 -60,-272.4 -60,-275
  Top Copper region: 65,250 65,240 63.86,234.26 60.61,229.39 55.74,226.14 50,225 50,225 44.26,226.14 39.39,229.39 36.14,234.26 35,240 35,240 35,250
  Top Copper region: -60,-250 -60,-240 -58.86,-234.26 -55.61,-229.39 -50.74,-226.14 -45,-225 -45,-225 -39.26,-226.14 -34.39,-229.39 -31.14,-234.26 -30,-240 -30,-240 -30,-250
  Top Copper region: 30,-250 30,-240 31.14,-234.26 34.39,-229.39 39.26,-226.14 45,-225 45,-225 50.74,-226.14 55.61,-229.39 58.86,-234.26 60,-240 60,-240 60,-250
  silkscreen extent -141,-291 141,315, body extent -129,-279 129,279, height 10
FP-BLM21SN300SN1D_0805-MFG [mm]
  rrect17% 0.6x1.25 smd paste+0 mask+0: 1(-0.9,0) 2(0.9,0)
  silkscreen extent -0.23,-0.72 0.23,0.72, body extent -1,-0.62 1,0.63, height 1.05
FP-ERJ-1GNJ5R1C_0201-MFG [mm]
  rrect40% 0.25x0.3 smd paste+0 mask+0: 1(-0.3,0) 2(0.3,0)
  silkscreen extent -0.33,-0.53 0.33,0.53, body extent -0.53,-0.27 0.53,0.26, height 0.25
FP-LQW03AW1N8C00D_0201-MFG [mm]
  rrect48% 0.21x0.4 smd paste+0 mask+0: 1(-0.22,0) 2(0.22,0)
  silkscreen extent -0.29,-0.58 0.29,0.58, body extent -0.43,-0.33 0.43,0.33, height 0.25
FP-TC1-1-13M+_SMT_3MM81_3MM81-MFG [mil]
  rrect13% 30x65 smd paste+0 mask+0: 1(-50,62.5) 2(0,62.5) 3(50,62.5) 4(50,-62.5) 6(-50,-62.5)
  silkscreen extent -78,-82 78,123, body extent -81,-99 81,99, height 10
IND_LQG15H [mm] "MuRata"
  rect 0.55x0.6 smd: 1(-0.475,0) 2(0.475,0)
  silkscreen extent -1.3,-0.3 -0.95,0.3, body extent -0.52,-0.27 0.52,0.27, height 0.55
Keystone5000 [mil] "For Keystone 500x miniature loop terminals"
  round 80 hole 40: 1(0,0)
  silkscreen extent -52,-52 52,52, body extent -49,-49 49,49, height 182
Keystone5001 [mil] "For Keystone 500x miniature loop terminals"
  round 80 hole 40: 1(0,0)
  silkscreen extent -52,-52 52,52, body extent -49,-49 49,49, height 182
Keystone5002 [mil] "For Keystone 500x miniature loop terminals"
  round 80 hole 40: 1(0,0)
  silkscreen extent -52,-52 52,52, body extent -49,-49 49,49, height 182
Keystone_2204 [mil] "HEX STANDOFF 4-40 ALUMINUM 3/4\""
  body extent -144,-125 144,125, height 750
Label_650x200 [mil] "Thermal Transfer Label"
  round 1 on Mech13: 0(0,0)
  silkscreen extent -325,-100 325,100, body extent -325,-100 325,100, height 1
LED_LTST-C170_Red [mm] "LITE-ON"
  rect 1.2x1.2 smd: 1(-1.05,0) 2(1.05,0)
  silkscreen extent -1.6,-1 2.2,1, body extent -1.05,-0.68 1.05,0.67, height 1.1
LED_LTST-C190_Red [mm] "Lite-On"
  rect 0.8x0.8 smd: 1(-0.75,0) 2(0.75,0)
  silkscreen extent -1.1,-0.8 1.8,0.8, body extent -0.85,-0.45 0.85,0.45, height 0.9
LMH81XX_COB [mm] "UQFN-12"
  rrect40% 0.6x0.25 smd: 1(-0.925,0.75) 2(-0.925,0.25) 3(-0.925,-0.25) 4(-0.925,-0.75) 7(0.925,-0.75) 8(0.925,-0.25) 9(0.925,0.25) 10(0.925,0.75)
  rrect40% 0.25x0.6 smd: 5(-0.25,-0.925) 6(0.25,-0.925) 11(0.25,0.925) 12(-0.25,0.925)
  rrect12% 0.8x0.8 smd paste-0.02: 13(0,0)
  body extent -1.05,-1.05 1.05,1.05, height 0.6
MNC_TCM1-83X+ [mm] "SMD, 6-Leads, Body 4.06x3.81mm, Pitch 1.27mm"
  rrect13% 0.76x1.65 smd: 1(-1.27,1.59) 2(0,1.59) 3(1.27,1.59) 4(1.27,-1.59) 5(0,-1.59) 6(-1.27,-1.59)
  silkscreen extent -2.2,-1.5 1.91,1.5, body extent -1.91,-2.03 1.9,2.03, height 4.06
Molex_0022284023 [mm] "Header, 2.54mm, 2x1, TH"
  rect 1.55x1.55 hole 1.02: 1(-1.27,0)
  round 1.55 hole 1.02: 2(1.27,0)
  silkscreen extent -2.54,-1.24 2.54,1.5, body extent -2.54,-1.24 2.54,1.24, height 8.4
Molex_0853050232 [mm] "Plug, 50 Ohm, Straight, SMT"
  rrect17% 0.6x1.3 smd: 1(0,3.05)
  rrect25% 0.4x0.4 smd: 2(0,-2.3)
  Top Copper region: -2.6,-2.6 -2.6,2.6 -1,2.6 -1,1.732 -1.732,1 -2,0 -1.732,-1 -1,-1.732 0,-2 1,-1.732 1.732,-1 2,0 1.732,1 1,1.732 1,1.732 1,2.6 2.6,2.6 2.6,-2.6
  body extent -2.5,-2.5 2.5,3.5, height 4.1
NHL0014B [mm] "WSON-14"
  rrect40% 0.6x0.25 smd: 1(-1.9,1.5) 2(-1.9,1) 3(-1.9,0.5) 4(-1.9,0) 5(-1.9,-0.5) 6(-1.9,-1) 7(-1.9,-1.5) 8(1.9,-1.5) 9(1.9,-1) 10(1.9,-0.5) 11(1.9,0) 12(1.9,0.5) 13(1.9,1) 14(1.9,1.5)
  rrect4% 2.6x3 smd paste-1.5: 15(0,0)
  silkscreen extent -2.15,-2.15 2.15,2.15, body extent -2,-2 2,2, height 0.81
NKD0064A [mm] "QFN, 64-Leads, Body 9x9mm, Pitch 0.5mm"
  rrect40% 0.6x0.25 smd: 1(-4.4,3.75) 2(-4.4,3.25) 3(-4.4,2.75) 4(-4.4,2.25) 5(-4.4,1.75) 6(-4.4,1.25) 7(-4.4,0.75) 8(-4.4,0.25) 9(-4.4,-0.25) 10(-4.4,-0.75) 11(-4.4,-1.25) 12(-4.4,-1.75) 13(-4.4,-2.25) 14(-4.4,-2.75) 15(-4.4,-3.25) 16(-4.4,-3.75) 33(4.4,-3.75) 34(4.4,-3.25) 35(4.4,-2.75) 36(4.4,-2.25) 37(4.4,-1.75) 38(4.4,-1.25) 39(4.4,-0.75) 40(4.4,-0.25) 41(4.4,0.25) 42(4.4,0.75) 43(4.4,1.25) 44(4.4,1.75) 45(4.4,2.25) 46(4.4,2.75) 47(4.4,3.25) 48(4.4,3.75)
  rrect40% 0.25x0.6 smd: 17(-3.75,-4.4) 18(-3.25,-4.4) 19(-2.75,-4.4) 20(-2.25,-4.4) 21(-1.75,-4.4) 22(-1.25,-4.4) 23(-0.75,-4.4) 24(-0.25,-4.4) 25(0.25,-4.4) 26(0.75,-4.4) 27(1.25,-4.4) 28(1.75,-4.4) 29(2.25,-4.4) 30(2.75,-4.4) 31(3.25,-4.4) 32(3.75,-4.4) 49(3.75,4.4) 50(3.25,4.4) 51(2.75,4.4) 52(2.25,4.4) 53(1.75,4.4) 54(1.25,4.4) 55(0.75,4.4) 56(0.25,4.4) 57(-0.25,4.4) 58(-0.75,4.4) 59(-1.25,4.4) 60(-1.75,4.4) 61(-2.25,4.4) 62(-2.75,4.4) 63(-3.25,4.4) 64(-3.75,4.4)
  rrect1% 7.2x7.2 smd paste-3.6: 65(0,0)
  silkscreen extent -4.65,-4.65 4.65,4.65, body extent -4.55,-4.55 4.55,4.55, height 0.81
"NY PMS 440 0025 PH" [mm] "4-40 nylon screw and mounting hole"
  round 8 hole 3.2: 1(0,0)
  body extent -3.3,-3.3 3.3,3.3, height 2.69
PBC03SAAN [mm] "Sullins 100mil, 1x3, 230 mil above insulator"
  rect 1.65x1.65 hole 1.016: 1(-2.54,0)
  round 1.65 hole 1.016: 2(0,0) 3(2.54,0)
  silkscreen extent -3.81,-1.27 3.81,1.27, body extent -3.81,-1.27 3.81,1.27, height 8.38
RGR0020A [mm] "QFN, 20-Leads, Body 3.5x3.5mm, Pitch 0.5mm, Thermal Pad 2.05x2.05mm, TI Recommended"
  rrect42% 0.6x0.24 smd: 1(-1.65,1) 2(-1.65,0.5) 3(-1.65,0) 4(-1.65,-0.5) 5(-1.65,-1) 11(1.65,-1) 12(1.65,-0.5) 13(1.65,0) 14(1.65,0.5) 15(1.65,1)
  rrect42% 0.24x0.6 smd: 6(-1,-1.65) 7(-0.5,-1.65) 8(0,-1.65) 9(0.5,-1.65) 10(1,-1.65) 16(1,1.65) 17(0.5,1.65) 18(0,1.65) 19(-0.5,1.65) 20(-1,1.65)
  rrect5% 2.05x2.05 smd paste-1.025: 21(0,0)
  silkscreen extent -1.97,-1.97 1.97,1.97, body extent -1.75,-1.75 1.75,1.75, height 1
RHA0040H [mm] "QFN, 40-Leads, Body 6x6mm, Pitch 0.5mm, Thermal Pad 4.15 x 4.15mm, TI Recommended"
  rrect40% 0.6x0.25 smd: 1(-2.9,2.25) 2(-2.9,1.75) 3(-2.9,1.25) 4(-2.9,0.75) 5(-2.9,0.25) 6(-2.9,-0.25) 7(-2.9,-0.75) 8(-2.9,-1.25) 9(-2.9,-1.75) 10(-2.9,-2.25) 21(2.9,-2.25) 22(2.9,-1.75) 23(2.9,-1.25) 24(2.9,-0.75) 25(2.9,-0.25) 26(2.9,0.25) 27(2.9,0.75) 28(2.9,1.25) 29(2.9,1.75) 30(2.9,2.25)
  rrect40% 0.25x0.6 smd: 11(-2.25,-2.9) 12(-1.75,-2.9) 13(-1.25,-2.9) 14(-0.75,-2.9) 15(-0.25,-2.9) 16(0.25,-2.9) 17(0.75,-2.9) 18(1.25,-2.9) 19(1.75,-2.9) 20(2.25,-2.9) 31(2.25,2.9) 32(1.75,2.9) 33(1.25,2.9) 34(0.75,2.9) 35(0.25,2.9) 36(-0.25,2.9) 37(-0.75,2.9) 38(-1.25,2.9) 39(-1.75,2.9) 40(-2.25,2.9)
  rrect8% 1.26x1.26 on Top Paste: 41(-1.46,-1.46) 41(-1.46,0) 41(-1.46,1.46) 41(0,-1.46) 41(0,0) 41(0,1.46) 41(1.46,-1.46) 41(1.46,0) 41(1.46,1.46)
  rrect2% 4.5x4.5 smd paste-2.5: 41(0,0)
  silkscreen extent -3.22,-3.22 3.22,3.23, body extent -3,-3 3,3, height 1
RNL0022A [mm] "VQFN-HR-22"
  rrect25% 0.6x0.4 smd: 1(-1.9,2) 17(1.9,2)
  rrect40% 0.6x0.25 smd: 2(-1.9,1.425) 3(-1.9,0.575) 5(-1.9,-1.175) 6(-1.9,-1.675) 7(-1.9,-2.175) 11(1.9,-2.175) 12(1.9,-1.675) 13(1.9,-1.175) 15(1.9,0.575) 16(1.9,1.425)
  rrect25% 1x0.4 smd paste-0.25: 4(-1.7,-0.25) 14(1.7,-0.25)
  rrect25% 0.4x0.4 on Top Paste: 4A(-2,-0.25) 4B(-1.4,-0.25) 14A(1.4,-0.25) 14B(2,-0.25)
  rrect25% 0.4x1.65 smd paste-0.25: 8(-1,-1.875) 10(1,-1.875)
  rrect25% 0.4x0.66 on Top Paste: 8A(-1,-1.445) 8B(-1,-2.305) 10A(1,-1.445) 10B(1,-2.305)
  rrect25% 0.4x3.15 smd paste-0.25: 9(0,-1.125)
  rrect25% 0.4x0.63 on Top Paste: 9A(0,0.12) 9B(0,-0.71) 9C(0,-1.54) 9D(0,-2.37)
  rrect40% 0.25x0.75 smd: 18(1,2.325) 19(0.5,2.325) 20(0,2.325) 21(-0.5,2.325) 22(-1,2.325)
  body extent -2,-2.5 2,2.5, height 0.9
RSV0016A [mm] "QFN, 16-Leads, Body 1.8x2.6mm, Pitch 0.4mm, TI Recommended"
  rect 0.7x0.2 smd: 1(-0.75,0.6)
  rect 0.6x0.2 smd: 2(-0.8,0.2) 3(-0.8,-0.2) 4(-0.8,-0.6) 9(0.8,-0.6) 10(0.8,-0.2) 11(0.8,0.2) 12(0.8,0.6)
  rect 0.2x0.6 smd: 5(-0.6,-1.2) 6(-0.2,-1.2) 7(0.2,-1.2) 8(0.6,-1.2) 13(0.6,1.2) 14(0.2,1.2) 15(-0.2,1.2) 16(-0.6,1.2)
  silkscreen extent -1.08,-1.33 1.08,1.45, body extent -0.92,-1.32 0.92,1.33, height 0.56
RTV0032A [mm] "WQFN-32"
  rrect42% 0.6x0.24 smd: 1(-2.4,1.75) 2(-2.4,1.25) 3(-2.4,0.75) 4(-2.4,0.25) 5(-2.4,-0.25) 6(-2.4,-0.75) 7(-2.4,-1.25) 8(-2.4,-1.75) 17(2.4,-1.75) 18(2.4,-1.25) 19(2.4,-0.75) 20(2.4,-0.25) 21(2.4,0.25) 22(2.4,0.75) 23(2.4,1.25) 24(2.4,1.75)
  rrect42% 0.24x0.6 smd: 9(-1.75,-2.4) 10(-1.25,-2.4) 11(-0.75,-2.4) 12(-0.25,-2.4) 13(0.25,-2.4) 14(0.75,-2.4) 15(1.25,-2.4) 16(1.75,-2.4) 25(1.75,2.4) 26(1.25,2.4) 27(0.75,2.4) 28(0.25,2.4) 29(-0.25,2.4) 30(-0.75,2.4) 31(-1.25,2.4) 32(-1.75,2.4)
  rrect3% 3.1x3.1 smd paste-1.55: 33(0,0)
  body extent -2.5,-2.5 2.5,2.5, height 0.8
